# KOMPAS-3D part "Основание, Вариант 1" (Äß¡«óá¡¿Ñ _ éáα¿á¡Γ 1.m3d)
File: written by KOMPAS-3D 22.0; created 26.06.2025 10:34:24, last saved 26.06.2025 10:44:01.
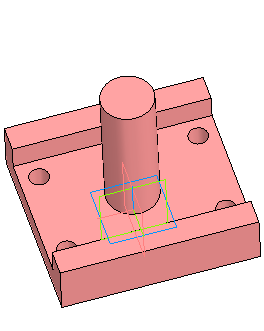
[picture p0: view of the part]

Document properties: Автор: Helen; Полное имя файла: D:\MY\WORK\MPEI\ППЭ_2025-2026\Варианты\Вар 1 СБ\Основание _ Вариант 1.m3d

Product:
- Body: Тело 1
    Масса: 5.328175
- Part/product: Основание  | designation Вариант 1
    Масса: 5.217114

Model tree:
1. Эскиз:1
2. Элемент выдавливания:1
     Расстояние 1 = 20
3. Эскиз:2  (with: Элемент выдавливания:1)
4. Элемент выдавливания:2
     Расстояние 1 = 20
5. Зеркальный массив:1
6. Экземпляр ( 1 )
7. Экземпляр ( 2 )  (with: Элемент выдавливания:2)
8. Эскиз:3  (with: Элемент выдавливания:1)
9. Элемент выдавливания:3
     Расстояние 1 = 110
10. Эскиз:4  (with: Элемент выдавливания:1, Элемент выдавливания:3)
11. Элемент выдавливания:4
     Расстояние 2 = 20
12. Зеркальный массив:2  (with: Экземпляр ( 1 ), Экземпляр ( 2 ), Элемент выдавливания:4)
13. Зеркальный массив:3  (with: Экземпляр ( 1 ), Экземпляр ( 2 ), Зеркальный массив:2, Элемент выдавливания:4)

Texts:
  Вариант 1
